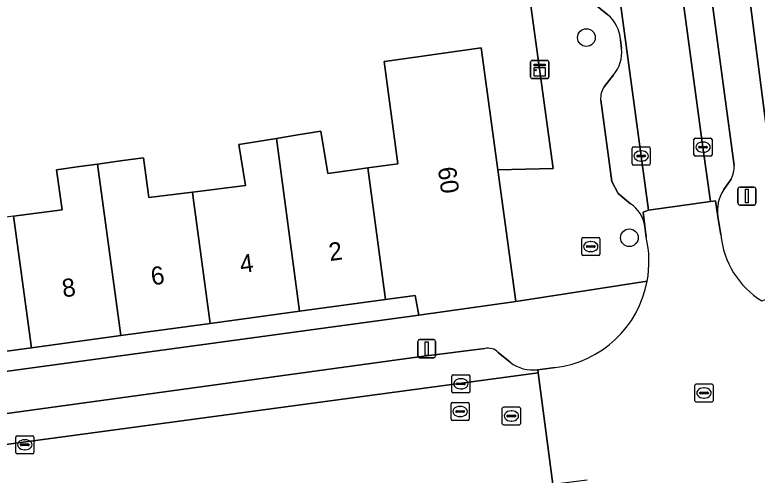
# Model space of a CAD drawing. Extents: x 163147 to 163550, y 380933 to 381639.
# Drawn here: x 163449.17 to 163490.26, y 381313.94 to 381339.43 of the extents above; entities that cross this region are included whole.
import ezdxf

# ---------------------------------------------------------------- set-up
doc = ezdxf.new("R2010")
doc.units = 0
for name, color, linetype in [('IMGEO_Boom', 7, 'Continuous'), ('IMGEO_Brandkraan', 7, 'Continuous'), ('IMGEO_Erf', 7, 'Continuous'), ('IMGEO_Kast', 7, 'Continuous'), ('IMGEO_Kolk', 7, 'Continuous'), ('IMGEO_Lichtmast', 7, 'Continuous'), ('IMGEO_Pand', 7, 'Continuous'), ('IMGEO_Pand_nummerreeks', 7, 'Continuous'), ('IMGEO_Parkeervlak_open', 7, 'Continuous'), ('IMGEO_Rijbaan_lokaal_open', 7, 'Continuous'), ('IMGEO_Rioolput', 7, 'Continuous'), ('IMGEO_Voetpad_open', 7, 'Continuous')]:
    doc.layers.add(name, color=color, linetype=linetype)

msp = doc.modelspace()

# ---------------------------------------------------------------- linework, layer by layer
at = {"layer": 'IMGEO_Boom'}
for centre in [(163480.812, 381338.174), (163483.189, 381327.09)]:
    msp.add_circle(centre, 0.489, dxfattribs=at)
at = {"layer": 'IMGEO_Brandkraan'}
for p, q in [((163480.551, 381326.176), (163480.551, 381327.028)), ((163480.626, 381327.102), (163481.478, 381327.102)), ((163481.039, 381326.882), (163481.064, 381326.882)), ((163481.552, 381327.028), (163481.552, 381326.176)), ((163480.81, 381326.596), (163480.81, 381326.608)), ((163481.248, 381326.559), (163480.85, 381326.559)), ((163480.853, 381326.645), (163481.251, 381326.645)), ((163481.062, 381326.322), (163481.037, 381326.322)), ((163481.294, 381326.608), (163481.294, 381326.596)), ((163481.478, 381326.102), (163480.626, 381326.102))]:
    msp.add_line(p, q, dxfattribs=at)
for points in [[(163480.551, 381326.176), (163480.551, 381327.028)], [(163480.626, 381327.102), (163481.478, 381327.102)], [(163481.552, 381327.028), (163481.552, 381326.176)], [(163481.478, 381326.102), (163480.626, 381326.102)]]:
    msp.add_lwpolyline(points, dxfattribs=at)
for centre, radius, start, end in [((163480.628, 381327.026), 0.0765, 91.552, 178.448), ((163480.628, 381327.026), 0.0765, 91.552, 178.448), ((163481.476, 381327.026), 0.0765, 1.552, 88.448), ((163481.476, 381327.026), 0.0765, 1.552, 88.448), ((163480.85, 381326.605), 0.0403, 85.8775, 175.7526), ((163480.847, 381326.595), 0.0366, 178.938, 274.7102), ((163481.251, 381326.602), 0.043, 264.8664, 352.4533), ((163481.255, 381326.607), 0.0386, 1.7309, 96.639), ((163480.628, 381326.178), 0.0765, 181.552, 268.448), ((163480.628, 381326.178), 0.0765, 181.552, 268.448), ((163481.476, 381326.178), 0.0765, 271.552, 358.448), ((163481.476, 381326.178), 0.0765, 271.552, 358.448)]:
    msp.add_arc(centre, radius, start, end, dxfattribs=at)
for centre, major_axis, ratio, start_param, end_param in [((163481.038, 381326.602), (-0.387, 0.002), 0.722429, 4.712389, 7.853982), ((163481.063, 381326.602), (-0.39, 0.002), 0.717154, 1.570796, 4.712389)]:
    msp.add_ellipse(centre, major_axis=major_axis, ratio=ratio, start_param=start_param, end_param=end_param, dxfattribs=at)
at = {"layer": 'IMGEO_Erf'}
for points in [[(163487.783, 381356.32), (163491.94, 381324.111), (163494.978, 381324.392), (163494.274, 381329.637), (163493.586, 381334.763), (163492.898, 381339.89)], [(163449.103, 381328.286), (163451.782, 381328.636), (163451.474, 381330.851), (163452.751, 381331.029), (163453.75, 381331.168), (163455.14, 381331.361), (163456.289, 381331.521), (163456.595, 381329.314), (163459.002, 381329.614), (163461.933, 381329.979), (163461.563, 381332.246), (163462.615, 381332.417), (163463.652, 381332.586), (163464.833, 381332.779), (163466.108, 381332.987), (163466.49, 381330.646), (163467.946, 381330.85), (163468.715, 381330.958), (163470.377, 381331.191), (163469.617, 381336.85), (163470.033, 381336.909), (163474.984, 381337.607), (163474.985, 381337.597), (163475.909, 381330.85), (163478.977, 381330.926), (163476.576, 381348.425)]]:
    msp.add_lwpolyline(points, dxfattribs=at)
msp.add_lwpolyline([(163471.53, 381322.796), (163471.329, 381323.896), (163469.693, 381323.673), (163464.936, 381323.024), (163459.992, 381322.35), (163455.044, 381321.675), (163450.096, 381321), (163445.148, 381320.325), (163440.2, 381319.65), (163435.252, 381318.975), (163431.298, 381318.436), (163430.615, 381318.343), (163430.304, 381318.301), (163430.452, 381317.213), (163430.746, 381317.253)], close=True, dxfattribs=at)
at = {"layer": 'IMGEO_Kast'}
for p, q in [((163477.725, 381335.98), (163477.725, 381336.821)), ((163477.725, 381336.821), (163477.725, 381335.98)), ((163477.8, 381336.905), (163478.641, 381336.905)), ((163478.641, 381336.905), (163477.8, 381336.905)), ((163478.725, 381336.83), (163478.725, 381335.989)), ((163478.725, 381335.989), (163478.725, 381336.83)), ((163478.65, 381335.905), (163477.809, 381335.905)), ((163477.809, 381335.905), (163478.65, 381335.905))]:
    msp.add_line(p, q, dxfattribs=at)
for points in [[(163477.92, 381336.695), (163478.52, 381336.695), (163478.52, 381336.61), (163477.92, 381336.61), (163477.92, 381336.695)], [(163477.92, 381336.52), (163478.52, 381336.52), (163478.52, 381336.031), (163477.92, 381336.031), (163477.92, 381336.52)]]:
    msp.add_lwpolyline(points, dxfattribs=at)
msp.add_circle((163478.004, 381336.369), 0.0377, dxfattribs=at)
for centre, start, end in [((163477.803, 381336.827), 92.4484, 184.2845), ((163477.803, 381336.827), 92.4484, 184.2845), ((163478.647, 381336.827), 2.4484, 94.2845), ((163478.647, 381336.827), 2.4484, 94.2845), ((163477.803, 381335.983), 182.4484, 274.2845), ((163477.803, 381335.983), 182.4484, 274.2845), ((163478.647, 381335.983), 272.4484, 4.2845), ((163478.647, 381335.983), 272.4484, 4.2845)]:
    msp.add_arc(centre, 0.0779, start, end, dxfattribs=at)
at = {"layer": 'IMGEO_Kolk'}
for p, q in [((163486.766, 381331.681), (163486.766, 381332.533)), ((163486.841, 381332.607), (163487.693, 381332.607)), ((163487.767, 381332.533), (163487.767, 381331.681)), ((163483.419, 381332.116), (163484.271, 381332.116)), ((163487.025, 381332.101), (163487.025, 381332.113)), ((163487.463, 381332.064), (163487.065, 381332.064)), ((163487.068, 381332.15), (163487.466, 381332.15)), ((163487.254, 381332.387), (163487.279, 381332.387)), ((163487.509, 381332.113), (163487.509, 381332.101)), ((163483.344, 381331.19), (163483.344, 381332.042)), ((163483.646, 381331.659), (163484.044, 381331.659)), ((163483.832, 381331.896), (163483.857, 381331.896)), ((163484.345, 381332.042), (163484.345, 381331.19)), ((163487.277, 381331.827), (163487.252, 381331.827)), ((163483.603, 381331.61), (163483.603, 381331.622)), ((163484.041, 381331.573), (163483.643, 381331.573)), ((163483.855, 381331.336), (163483.83, 381331.336)), ((163484.087, 381331.622), (163484.087, 381331.61)), ((163487.693, 381331.607), (163486.841, 381331.607)), ((163484.271, 381331.116), (163483.419, 381331.116)), ((163473.366, 381318.577), (163473.366, 381319.429)), ((163473.441, 381319.503), (163474.293, 381319.503)), ((163474.367, 381319.429), (163474.367, 381318.577)), ((163473.625, 381318.997), (163473.625, 381319.009)), ((163474.063, 381318.96), (163473.665, 381318.96)), ((163473.668, 381319.046), (163474.066, 381319.046)), ((163473.854, 381319.283), (163473.879, 381319.283)), ((163474.109, 381319.009), (163474.109, 381318.997)), ((163474.293, 381318.503), (163473.441, 381318.503)), ((163473.877, 381318.723), (163473.852, 381318.723)), ((163449.219, 381315.203), (163449.219, 381316.055)), ((163449.294, 381316.129), (163450.146, 381316.129)), ((163450.22, 381316.055), (163450.22, 381315.203)), ((163449.478, 381315.623), (163449.478, 381315.635)), ((163449.521, 381315.672), (163449.919, 381315.672)), ((163449.707, 381315.909), (163449.732, 381315.909)), ((163449.962, 381315.635), (163449.962, 381315.623)), ((163449.916, 381315.586), (163449.518, 381315.586)), ((163449.73, 381315.349), (163449.705, 381315.349)), ((163450.146, 381315.129), (163449.294, 381315.129))]:
    msp.add_line(p, q, dxfattribs=at)
for points in [[(163486.766, 381331.681), (163486.766, 381332.533)], [(163486.841, 381332.607), (163487.693, 381332.607)], [(163487.767, 381332.533), (163487.767, 381331.681)], [(163483.419, 381332.116), (163484.271, 381332.116)], [(163483.344, 381331.19), (163483.344, 381332.042)], [(163484.345, 381332.042), (163484.345, 381331.19)], [(163487.693, 381331.607), (163486.841, 381331.607)], [(163484.271, 381331.116), (163483.419, 381331.116)], [(163473.366, 381318.577), (163473.366, 381319.429)], [(163473.441, 381319.503), (163474.293, 381319.503)], [(163474.367, 381319.429), (163474.367, 381318.577)], [(163474.293, 381318.503), (163473.441, 381318.503)], [(163449.219, 381315.203), (163449.219, 381316.055)], [(163449.294, 381316.129), (163450.146, 381316.129)], [(163450.22, 381316.055), (163450.22, 381315.203)], [(163450.146, 381315.129), (163449.294, 381315.129)]]:
    msp.add_lwpolyline(points, dxfattribs=at)
for centre, radius, start, end in [((163486.843, 381332.531), 0.0765, 91.552, 178.448), ((163486.843, 381332.531), 0.0765, 91.552, 178.448), ((163487.691, 381332.531), 0.0765, 1.552, 88.448), ((163487.691, 381332.531), 0.0765, 1.552, 88.448), ((163483.421, 381332.04), 0.0765, 91.552, 178.448), ((163483.421, 381332.04), 0.0765, 91.552, 178.448), ((163484.269, 381332.04), 0.0765, 1.552, 88.448), ((163484.269, 381332.04), 0.0765, 1.552, 88.448), ((163487.065, 381332.11), 0.0403, 85.8775, 175.7526), ((163487.062, 381332.1), 0.0366, 178.938, 274.7102), ((163487.466, 381332.107), 0.043, 264.8664, 352.4533), ((163487.47, 381332.112), 0.0386, 1.7309, 96.639), ((163483.643, 381331.619), 0.0403, 85.8775, 175.7526), ((163484.048, 381331.621), 0.0386, 1.7309, 96.639), ((163486.843, 381331.683), 0.0765, 181.552, 268.448), ((163486.843, 381331.683), 0.0765, 181.552, 268.448), ((163487.691, 381331.683), 0.0765, 271.552, 358.448), ((163487.691, 381331.683), 0.0765, 271.552, 358.448), ((163483.64, 381331.609), 0.0366, 178.938, 274.7102), ((163484.044, 381331.616), 0.043, 264.8664, 352.4533), ((163483.421, 381331.192), 0.0765, 181.552, 268.448), ((163483.421, 381331.192), 0.0765, 181.552, 268.448), ((163484.269, 381331.192), 0.0765, 271.552, 358.448), ((163484.269, 381331.192), 0.0765, 271.552, 358.448), ((163473.443, 381319.427), 0.0765, 91.552, 178.448), ((163473.443, 381319.427), 0.0765, 91.552, 178.448), ((163474.291, 381319.427), 0.0765, 1.552, 88.448), ((163474.291, 381319.427), 0.0765, 1.552, 88.448), ((163473.665, 381319.006), 0.0403, 85.8775, 175.7526), ((163473.662, 381318.996), 0.0366, 178.938, 274.7102), ((163474.066, 381319.003), 0.043, 264.8664, 352.4533), ((163474.07, 381319.008), 0.0386, 1.7309, 96.639), ((163473.443, 381318.579), 0.0765, 181.552, 268.448), ((163473.443, 381318.579), 0.0765, 181.552, 268.448), ((163474.291, 381318.579), 0.0765, 271.552, 358.448), ((163474.291, 381318.579), 0.0765, 271.552, 358.448), ((163449.296, 381316.053), 0.0765, 91.552, 178.448), ((163449.296, 381316.053), 0.0765, 91.552, 178.448), ((163450.144, 381316.053), 0.0765, 1.552, 88.448), ((163450.144, 381316.053), 0.0765, 1.552, 88.448), ((163449.518, 381315.632), 0.0403, 85.8775, 175.7526), ((163449.515, 381315.622), 0.0366, 178.938, 274.7102), ((163449.919, 381315.629), 0.043, 264.8664, 352.4533), ((163449.923, 381315.634), 0.0386, 1.7309, 96.639), ((163449.296, 381315.205), 0.0765, 181.552, 268.448), ((163449.296, 381315.205), 0.0765, 181.552, 268.448), ((163450.144, 381315.205), 0.0765, 271.552, 358.448), ((163450.144, 381315.205), 0.0765, 271.552, 358.448)]:
    msp.add_arc(centre, radius, start, end, dxfattribs=at)
for centre, major_axis, ratio, start_param, end_param in [((163487.253, 381332.107), (-0.387, 0.002), 0.722429, 4.712389, 7.853982), ((163487.278, 381332.107), (-0.39, 0.002), 0.717154, 1.570796, 4.712389), ((163483.831, 381331.616), (-0.387, 0.002), 0.722429, 4.712389, 7.853982), ((163483.856, 381331.616), (-0.39, 0.002), 0.717154, 1.570796, 4.712389), ((163473.853, 381319.003), (-0.387, 0.002), 0.722429, 4.712389, 7.853982), ((163473.878, 381319.003), (-0.39, 0.002), 0.717154, 1.570796, 4.712389), ((163449.706, 381315.629), (-0.387, 0.002), 0.722429, 4.712389, 7.853982), ((163449.731, 381315.629), (-0.39, 0.002), 0.717154, 1.570796, 4.712389)]:
    msp.add_ellipse(centre, major_axis=major_axis, ratio=ratio, start_param=start_param, end_param=end_param, dxfattribs=at)
at = {"layer": 'IMGEO_Lichtmast'}
for p, q in [((163489.202, 381328.999), (163489.202, 381329.799)), ((163489.202, 381329.799), (163489.202, 381328.999)), ((163489.302, 381329.899), (163490.092, 381329.899)), ((163490.092, 381329.899), (163489.302, 381329.899)), ((163490.192, 381329.799), (163490.192, 381328.999)), ((163490.192, 381328.999), (163490.192, 381329.799)), ((163490.092, 381328.899), (163489.302, 381328.899)), ((163489.302, 381328.899), (163490.092, 381328.899)), ((163471.573, 381321.449), (163472.363, 381321.449)), ((163472.363, 381321.449), (163471.573, 381321.449)), ((163471.473, 381320.549), (163471.473, 381321.349)), ((163471.473, 381321.349), (163471.473, 381320.549)), ((163472.463, 381321.349), (163472.463, 381320.549)), ((163472.463, 381320.549), (163472.463, 381321.349)), ((163472.363, 381320.449), (163471.573, 381320.449)), ((163471.573, 381320.449), (163472.363, 381320.449))]:
    msp.add_line(p, q, dxfattribs=at)
for points in [[(163489.622, 381329.774), (163489.772, 381329.774), (163489.772, 381329.024), (163489.622, 381329.024), (163489.622, 381329.774)], [(163471.893, 381321.324), (163472.043, 381321.324), (163472.043, 381320.574), (163471.893, 381320.574), (163471.893, 381321.324)]]:
    msp.add_lwpolyline(points, dxfattribs=at)
for centre, start, end in [((163489.302, 381329.799), 90, 180), ((163489.302, 381329.799), 90, 180), ((163490.092, 381329.799), 0, 90), ((163490.092, 381329.799), 360, 90), ((163489.302, 381328.999), 180, 270), ((163489.302, 381328.999), 180, 270), ((163490.092, 381328.999), 270, 0), ((163490.092, 381328.999), 270, 0), ((163471.573, 381321.349), 90, 180), ((163471.573, 381321.349), 90, 180), ((163472.363, 381321.349), 0, 90), ((163472.363, 381321.349), 360, 90), ((163471.573, 381320.549), 180, 270), ((163471.573, 381320.549), 180, 270), ((163472.363, 381320.549), 270, 0), ((163472.363, 381320.549), 270, 0)]:
    msp.add_arc(centre, 0.1, start, end, dxfattribs=at)
at = {"layer": 'IMGEO_Pand'}
for points in [[(163475.909, 381330.85), (163474.985, 381337.597), (163474.984, 381337.607), (163470.033, 381336.909), (163469.617, 381336.85), (163470.377, 381331.191), (163468.715, 381330.958), (163469.693, 381323.673), (163471.329, 381323.896), (163471.53, 381322.796), (163476.907, 381323.561)], [(163468.715, 381330.958), (163467.946, 381330.85), (163466.49, 381330.646), (163466.108, 381332.987), (163464.833, 381332.779), (163463.652, 381332.586), (163464.936, 381323.024), (163469.693, 381323.673)], [(163463.652, 381332.586), (163462.615, 381332.417), (163461.563, 381332.246), (163461.933, 381329.979), (163459.002, 381329.614), (163459.024, 381329.451), (163459.992, 381322.35), (163464.936, 381323.024)], [(163459.002, 381329.614), (163456.595, 381329.314), (163456.289, 381331.521), (163455.14, 381331.361), (163453.75, 381331.168), (163455.044, 381321.675), (163459.992, 381322.35), (163459.024, 381329.451)], [(163453.75, 381331.168), (163452.751, 381331.029), (163451.474, 381330.851), (163451.782, 381328.636), (163449.103, 381328.286), (163449.139, 381328.019), (163450.096, 381321), (163455.044, 381321.675)], [(163449.103, 381328.286), (163446.715, 381327.975), (163446.402, 381330.21), (163445.277, 381330.052), (163443.849, 381329.852), (163445.148, 381320.325), (163450.096, 381321), (163449.139, 381328.019)]]:
    msp.add_lwpolyline(points, close=True, dxfattribs=at)
at = {"layer": 'IMGEO_Parkeervlak_open'}
for points in [[(163484.055, 381327.735), (163483.954, 381328.514), (163484.25, 381328.608), (163483.846, 381331.616), (163481.014, 381352.472), (163478.387, 381372.049), (163475.613, 381392.784), (163475.57, 381392.982), (163475.27, 381392.965), (163474.636, 381397.753), (163474.95, 381397.812), (163472.424, 381416.369), (163471.932, 381420.183), (163469.84, 381435.559), (163467.375, 381453.632), (163467.333, 381454.278), (163467.014, 381454.229), (163466.392, 381459.15), (163466.653, 381459.2), (163466.627, 381459.524), (163464.446, 381475.737), (163461.659, 381496.063), (163461.275, 381499.196)], [(163479.015, 381395.662), (163479.31, 381393.474), (163479.013, 381393.424), (163479.069, 381393.155), (163481.839, 381372.532), (163484.475, 381352.776), (163487.265, 381332.107), (163487.676, 381329.103), (163487.95, 381329.137), (163488.089, 381328.26)], [(163488.99, 381331.093), (163484.987, 381360.827)], [(163481.216, 381340.054), (163481.99, 381339.432)], [(163482.697, 381338.055), (163482.749, 381337.565)], [(163482.303, 381336.105), (163481.795, 381335.449)], [(163481.601, 381334.711), (163482.212, 381330.196), (163482.566, 381329.531), (163483.261, 381328.967)], [(163488.41, 381329.753), (163488.828, 381330.336)], [(163475.188, 381320.95), (163471.819, 381320.534)], [(163476.587, 381320.197), (163475.934, 381320.744)], [(163471.819, 381320.534), (163424.95, 381314.09)], [(163478.14, 381319.616), (163478.118, 381319.785)], [(163422.756, 381312.154), (163478.14, 381319.616)]]:
    msp.add_lwpolyline(points, dxfattribs=at)
for centre, radius, start, end in [((163480.738, 381337.919), 1.963, 3.96, 50.3951), ((163480.918, 381337.326), 1.847, 318.599, 7.4273), ((163482.766, 381334.799), 1.169, 146.2182, 184.3253), ((163487.528, 381331.01), 1.465, 332.598, 3.2435), ((163490.237, 381328.579), 2.171, 147.2788, 188.4531), ((163482.286, 381327.467), 1.789, 8.6173, 56.9847), ((163475.38, 381320.193), 0.781, 44.859, 104.2672), ((163477.844, 381321.816), 2.05, 232.1868, 277.6897)]:
    msp.add_arc(centre, radius, start, end, dxfattribs=at)
at = {"layer": 'IMGEO_Rijbaan_lokaal_open'}
for points in [[(163475.57, 381392.982), (163475.613, 381392.784), (163478.387, 381372.049), (163481.014, 381352.472), (163483.846, 381331.616), (163484.25, 381328.608), (163487.676, 381329.103), (163487.265, 381332.107), (163484.475, 381352.776), (163481.839, 381372.532), (163479.069, 381393.155), (163479.013, 381393.424)], [(163478.952, 381313.454), (163478.14, 381319.616), (163422.756, 381312.154), (163422.382, 381312.104), (163422.173, 381312.093), (163422.932, 381305.852), (163423.08, 381305.875), (163472.145, 381312.545), (163474.614, 381312.883)]]:
    msp.add_lwpolyline(points, close=True, dxfattribs=at)
for points in [[(163488.257, 381327.246), (163488.089, 381328.26), (163487.95, 381329.137), (163487.676, 381329.103), (163484.25, 381328.608), (163483.954, 381328.514), (163484.055, 381327.735), (163484.118, 381327.118)], [(163479.082, 381319.899), (163478.118, 381319.785), (163478.14, 381319.616), (163478.952, 381313.454), (163480.848, 381313.687)]]:
    msp.add_lwpolyline(points, dxfattribs=at)
for centre, radius, start, end in [((163478.37, 381325.767), 5.905, 349.4612, 13.2252), ((163493.064, 381327.696), 4.828, 185.347, 238.2884), ((163478.363, 381325.767), 5.911, 276.9867, 349.4773)]:
    msp.add_arc(centre, radius, start, end, dxfattribs=at)
at = {"layer": 'IMGEO_Rioolput'}
for p, q in [((163486.82, 381318.067), (163486.82, 381318.919)), ((163486.895, 381318.993), (163487.747, 381318.993)), ((163487.821, 381318.919), (163487.821, 381318.067)), ((163487.079, 381318.487), (163487.079, 381318.499)), ((163487.122, 381318.536), (163487.52, 381318.536)), ((163487.308, 381318.773), (163487.333, 381318.773)), ((163487.563, 381318.499), (163487.563, 381318.487)), ((163487.517, 381318.45), (163487.119, 381318.45)), ((163487.331, 381318.213), (163487.306, 381318.213)), ((163473.32, 381317.042), (163473.32, 381317.894)), ((163473.395, 381317.968), (163474.247, 381317.968)), ((163473.808, 381317.748), (163473.833, 381317.748)), ((163474.321, 381317.894), (163474.321, 381317.042)), ((163476.231, 381317.719), (163477.083, 381317.719)), ((163487.747, 381317.993), (163486.895, 381317.993)), ((163473.579, 381317.462), (163473.579, 381317.474)), ((163474.017, 381317.425), (163473.619, 381317.425)), ((163473.622, 381317.511), (163474.02, 381317.511)), ((163474.063, 381317.474), (163474.063, 381317.462)), ((163476.156, 381316.793), (163476.156, 381317.645)), ((163476.458, 381317.262), (163476.856, 381317.262)), ((163476.644, 381317.499), (163476.669, 381317.499)), ((163477.157, 381317.645), (163477.157, 381316.793)), ((163474.247, 381316.968), (163473.395, 381316.968)), ((163473.831, 381317.188), (163473.806, 381317.188)), ((163476.415, 381317.213), (163476.415, 381317.225)), ((163476.853, 381317.176), (163476.455, 381317.176)), ((163476.667, 381316.939), (163476.642, 381316.939)), ((163476.899, 381317.225), (163476.899, 381317.213)), ((163477.083, 381316.719), (163476.231, 381316.719))]:
    msp.add_line(p, q, dxfattribs=at)
for points in [[(163486.82, 381318.067), (163486.82, 381318.919)], [(163486.895, 381318.993), (163487.747, 381318.993)], [(163487.821, 381318.919), (163487.821, 381318.067)], [(163473.32, 381317.042), (163473.32, 381317.894)], [(163473.395, 381317.968), (163474.247, 381317.968)], [(163474.321, 381317.894), (163474.321, 381317.042)], [(163476.231, 381317.719), (163477.083, 381317.719)], [(163487.747, 381317.993), (163486.895, 381317.993)], [(163476.156, 381316.793), (163476.156, 381317.645)], [(163477.157, 381317.645), (163477.157, 381316.793)], [(163474.247, 381316.968), (163473.395, 381316.968)], [(163477.083, 381316.719), (163476.231, 381316.719)]]:
    msp.add_lwpolyline(points, dxfattribs=at)
for centre, radius, start, end in [((163486.897, 381318.917), 0.0765, 91.552, 178.448), ((163486.897, 381318.917), 0.0765, 91.552, 178.448), ((163487.745, 381318.917), 0.0765, 1.552, 88.448), ((163487.745, 381318.917), 0.0765, 1.552, 88.448), ((163487.119, 381318.496), 0.0403, 85.8775, 175.7526), ((163487.524, 381318.498), 0.0386, 1.7309, 96.639), ((163487.116, 381318.486), 0.0366, 178.938, 274.7102), ((163487.52, 381318.493), 0.043, 264.8664, 352.4533), ((163473.397, 381317.892), 0.0765, 91.552, 178.448), ((163473.397, 381317.892), 0.0765, 91.552, 178.448), ((163474.245, 381317.892), 0.0765, 1.552, 88.448), ((163474.245, 381317.892), 0.0765, 1.552, 88.448), ((163476.233, 381317.643), 0.0765, 91.552, 178.448), ((163476.233, 381317.643), 0.0765, 91.552, 178.448), ((163477.081, 381317.643), 0.0765, 1.552, 88.448), ((163477.081, 381317.643), 0.0765, 1.552, 88.448), ((163486.897, 381318.069), 0.0765, 181.552, 268.448), ((163486.897, 381318.069), 0.0765, 181.552, 268.448), ((163487.745, 381318.069), 0.0765, 271.552, 358.448), ((163487.745, 381318.069), 0.0765, 271.552, 358.448), ((163473.619, 381317.471), 0.0403, 85.8775, 175.7526), ((163473.616, 381317.461), 0.0366, 178.938, 274.7102), ((163474.02, 381317.468), 0.043, 264.8664, 352.4533), ((163474.024, 381317.473), 0.0386, 1.7309, 96.639), ((163476.455, 381317.222), 0.0403, 85.8775, 175.7526), ((163476.86, 381317.224), 0.0386, 1.7309, 96.639), ((163473.397, 381317.044), 0.0765, 181.552, 268.448), ((163473.397, 381317.044), 0.0765, 181.552, 268.448), ((163474.245, 381317.044), 0.0765, 271.552, 358.448), ((163474.245, 381317.044), 0.0765, 271.552, 358.448), ((163476.452, 381317.212), 0.0366, 178.938, 274.7102), ((163476.856, 381317.219), 0.043, 264.8664, 352.4533), ((163476.233, 381316.795), 0.0765, 181.552, 268.448), ((163476.233, 381316.795), 0.0765, 181.552, 268.448), ((163477.081, 381316.795), 0.0765, 271.552, 358.448), ((163477.081, 381316.795), 0.0765, 271.552, 358.448)]:
    msp.add_arc(centre, radius, start, end, dxfattribs=at)
for centre, major_axis, ratio, start_param, end_param in [((163487.307, 381318.493), (-0.387, 0.002), 0.722429, 4.712389, 7.853982), ((163487.332, 381318.493), (-0.39, 0.002), 0.717154, 1.570796, 4.712389), ((163473.807, 381317.468), (-0.387, 0.002), 0.722429, 4.712389, 7.853982), ((163473.832, 381317.468), (-0.39, 0.002), 0.717154, 1.570796, 4.712389), ((163476.643, 381317.219), (-0.387, 0.002), 0.722429, 4.712389, 7.853982), ((163476.668, 381317.219), (-0.39, 0.002), 0.717154, 1.570796, 4.712389)]:
    msp.add_ellipse(centre, major_axis=major_axis, ratio=ratio, start_param=start_param, end_param=end_param, dxfattribs=at)
at = {"layer": 'IMGEO_Voetpad_open'}
for points in [[(163490.526, 381323.589), (163491.94, 381324.111), (163487.783, 381356.32), (163487.612, 381356.297), (163487.586, 381356.488), (163486.908, 381361.54), (163486.877, 381361.772), (163487.388, 381361.841), (163486.74, 381366.662), (163486.09, 381371.504), (163485.566, 381371.433), (163485.538, 381371.644), (163484.859, 381376.696), (163484.837, 381376.861), (163474.607, 381453.41)], [(163462.651, 381451.92), (163472.061, 381381.768), (163472.257, 381380.311), (163472.929, 381375.301), (163472.951, 381375.135), (163473.63, 381370.079), (163473.666, 381369.808), (163473.176, 381369.742), (163473.819, 381364.957), (163474.469, 381360.117), (163474.977, 381360.185), (163475.006, 381359.969), (163475.685, 381354.914), (163475.706, 381354.758), (163476.394, 381349.749), (163476.576, 381348.425), (163478.977, 381330.926), (163475.909, 381330.85), (163476.907, 381323.561), (163484.175, 381324.687)], [(163484.987, 381360.827), (163488.99, 381331.093)], [(163481.99, 381339.432), (163481.216, 381340.054)], [(163482.749, 381337.565), (163482.697, 381338.055)], [(163481.795, 381335.449), (163482.303, 381336.105)], [(163483.261, 381328.967), (163482.566, 381329.531), (163482.212, 381330.196), (163481.601, 381334.711)], [(163488.828, 381330.336), (163488.41, 381329.753)], [(163488.089, 381328.26), (163488.257, 381327.246)], [(163484.118, 381327.118), (163484.055, 381327.735)], [(163484.175, 381324.687), (163476.907, 381323.561), (163471.53, 381322.796), (163430.746, 381317.253), (163430.452, 381317.213), (163425.45, 381316.538), (163420.413, 381315.884), (163417.323, 381315.065)], [(163471.819, 381320.534), (163475.188, 381320.95)], [(163475.934, 381320.744), (163476.587, 381320.197)], [(163424.95, 381314.09), (163471.819, 381320.534)], [(163478.118, 381319.785), (163479.082, 381319.899)]]:
    msp.add_lwpolyline(points, dxfattribs=at)
for centre, radius, start, end in [((163480.738, 381337.919), 1.963, 3.96, 50.3951), ((163480.918, 381337.326), 1.847, 318.599, 7.4273), ((163482.766, 381334.799), 1.169, 146.2182, 184.3253), ((163487.528, 381331.01), 1.465, 332.598, 3.2435), ((163490.237, 381328.579), 2.171, 147.2788, 188.4531), ((163482.286, 381327.467), 1.789, 8.6173, 56.9847), ((163478.37, 381325.767), 5.905, 349.4612, 13.2252), ((163493.064, 381327.696), 4.828, 185.347, 238.2884), ((163478.363, 381325.767), 5.911, 276.9867, 349.4773), ((163475.38, 381320.193), 0.781, 44.859, 104.2672), ((163477.844, 381321.816), 2.05, 232.1868, 277.6897)]:
    msp.add_arc(centre, radius, start, end, dxfattribs=at)

# ---------------------------------------------------------------- texts
at = {"layer": 'IMGEO_Pand_nummerreeks'}
for s, rotation, p in [('60', 277.7977, (163472.585, 381330.955)), ('2', 7.7693, (163466.615, 381325.796)), ('4', 7.7693, (163461.693, 381325.125)), ('6', 7.7693, (163456.77, 381324.453)), ('8', 7.7693, (163451.85, 381323.783))]:
    msp.add_text(s, height=1, rotation=rotation, dxfattribs=at).set_placement(p)

doc.saveas('drawing.dxf')
